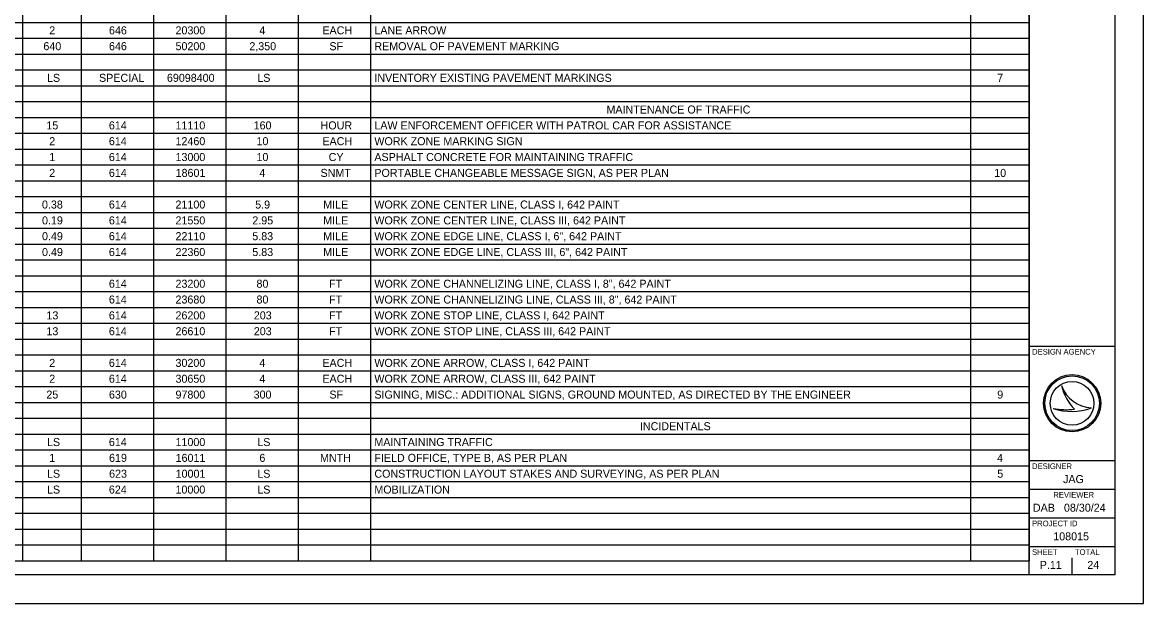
# Model space of a CAD drawing. Extents: x 0 to 34, y 0 to 22.
# Drawn here: x 14.4 to 34, y 0 to 10.16 of the extents above; entities that cross this region are included whole.
import ezdxf

# ---------------------------------------------------------------- set-up
doc = ezdxf.new("R2010")
doc.units = 0
for name, color, linetype in [('Default', 7, 'Continuous'), ('SH_Border', 7, 'Continuous'), ('SH_Cut_Line', 7, 'Continuous'), ('SH_Data', 7, 'Continuous')]:
    doc.layers.add(name, color=color, linetype=linetype)

msp = doc.modelspace()

# ---------------------------------------------------------------- linework, layer by layer
at = {"layer": 'Default'}
for p, q in [((14.396, 10.432), (14.396, 10.155)), ((15.424, 10.432), (15.424, 10.155)), ((16.689, 10.432), (16.689, 10.155)), ((17.954, 10.432), (17.954, 10.155)), ((19.219, 10.432), (19.219, 10.155)), ((20.484, 10.432), (20.484, 10.155)), ((30.972, 10.432), (30.972, 10.155)), ((32, 10.432), (32, 10.155)), ((13.368, 10.155), (14.396, 10.155)), ((14.396, 10.155), (30.972, 10.155)), ((14.396, 10.155), (14.396, 9.878)), ((15.424, 10.155), (15.424, 9.878)), ((16.689, 10.155), (16.689, 9.878)), ((17.954, 10.155), (17.954, 9.878)), ((19.219, 10.155), (19.219, 9.878)), ((20.484, 10.155), (20.484, 9.878)), ((30.972, 10.155), (32, 10.155)), ((30.972, 10.155), (30.972, 9.878)), ((32, 10.155), (32, 9.878)), ((13.368, 9.878), (14.396, 9.878)), ((14.396, 9.878), (30.972, 9.878)), ((14.396, 9.878), (14.396, 9.048)), ((15.424, 9.878), (15.424, 9.048)), ((16.689, 9.878), (16.689, 9.048)), ((17.954, 9.878), (17.954, 9.048)), ((19.219, 9.878), (19.219, 9.048)), ((20.484, 9.878), (20.484, 9.048)), ((30.972, 9.878), (32, 9.878)), ((30.972, 9.878), (30.972, 9.048)), ((32, 9.878), (32, 9.048)), ((13.368, 9.602), (14.396, 9.602)), ((14.396, 9.602), (30.972, 9.602)), ((30.972, 9.602), (32, 9.602)), ((13.368, 9.325), (14.396, 9.325)), ((14.396, 9.325), (30.972, 9.325)), ((30.972, 9.325), (32, 9.325)), ((13.368, 9.048), (14.396, 9.048)), ((14.396, 9.048), (30.972, 9.048)), ((14.396, 9.048), (14.396, 8.495)), ((15.424, 9.048), (15.424, 8.495)), ((16.689, 9.048), (16.689, 8.495)), ((17.954, 9.048), (17.954, 8.495)), ((19.219, 9.048), (19.219, 8.495)), ((20.484, 9.048), (20.484, 8.495)), ((30.972, 9.048), (32, 9.048)), ((30.972, 9.048), (30.972, 8.495)), ((32, 9.048), (32, 8.495)), ((13.368, 8.772), (14.396, 8.772)), ((14.396, 8.772), (30.972, 8.772)), ((30.972, 8.772), (32, 8.772)), ((13.368, 8.495), (14.396, 8.495)), ((14.396, 8.495), (30.972, 8.495)), ((14.396, 8.495), (14.396, 7.665)), ((15.424, 8.495), (15.424, 7.665)), ((16.689, 8.495), (16.689, 7.665)), ((17.954, 8.495), (17.954, 7.665)), ((19.219, 8.495), (19.219, 7.665)), ((20.484, 8.495), (20.484, 7.665)), ((30.972, 8.495), (32, 8.495)), ((30.972, 8.495), (30.972, 7.665)), ((32, 8.495), (32, 7.665)), ((13.368, 8.218), (14.396, 8.218)), ((14.396, 8.218), (30.972, 8.218)), ((30.972, 8.218), (32, 8.218)), ((13.368, 7.941), (14.396, 7.941)), ((14.396, 7.941), (30.972, 7.941)), ((30.972, 7.941), (32, 7.941)), ((13.368, 7.665), (14.396, 7.665)), ((14.396, 7.665), (30.972, 7.665)), ((14.396, 7.665), (14.396, 7.111)), ((15.424, 7.665), (15.424, 7.111)), ((16.689, 7.665), (16.689, 7.111)), ((17.954, 7.665), (17.954, 7.111)), ((19.219, 7.665), (19.219, 7.111)), ((20.484, 7.665), (20.484, 7.111)), ((30.972, 7.665), (32, 7.665)), ((30.972, 7.665), (30.972, 7.111)), ((32, 7.665), (32, 7.111)), ((13.368, 7.388), (14.396, 7.388)), ((14.396, 7.388), (30.972, 7.388)), ((30.972, 7.388), (32, 7.388)), ((13.368, 7.111), (14.396, 7.111)), ((14.396, 7.111), (30.972, 7.111)), ((14.396, 7.111), (14.396, 6.281)), ((15.424, 7.111), (15.424, 6.281)), ((16.689, 7.111), (16.689, 6.281)), ((17.954, 7.111), (17.954, 6.281)), ((19.219, 7.111), (19.219, 6.281)), ((20.484, 7.111), (20.484, 6.281)), ((30.972, 7.111), (32, 7.111)), ((30.972, 7.111), (30.972, 6.281)), ((32, 7.111), (32, 6.281)), ((13.368, 6.835), (14.396, 6.835)), ((14.396, 6.835), (30.972, 6.835)), ((30.972, 6.835), (32, 6.835)), ((13.368, 6.558), (14.396, 6.558)), ((14.396, 6.558), (30.972, 6.558)), ((30.972, 6.558), (32, 6.558)), ((13.368, 6.281), (14.396, 6.281)), ((14.396, 6.281), (30.972, 6.281)), ((14.396, 6.281), (14.396, 5.174)), ((15.424, 6.281), (15.424, 5.174)), ((16.689, 6.281), (16.689, 5.174)), ((17.954, 6.281), (17.954, 5.174)), ((19.219, 6.281), (19.219, 5.174)), ((20.484, 6.281), (20.484, 5.174)), ((30.972, 6.281), (32, 6.281)), ((30.972, 6.281), (30.972, 5.174)), ((32, 6.281), (32, 5.174)), ((13.368, 6.004), (14.396, 6.004)), ((14.396, 6.004), (30.972, 6.004)), ((30.972, 6.004), (32, 6.004)), ((13.368, 5.728), (14.396, 5.728)), ((14.396, 5.728), (30.972, 5.728)), ((30.972, 5.728), (32, 5.728)), ((13.368, 5.451), (14.396, 5.451)), ((14.396, 5.451), (30.972, 5.451)), ((30.972, 5.451), (32, 5.451)), ((13.368, 5.174), (14.396, 5.174)), ((14.396, 5.174), (30.972, 5.174)), ((14.396, 5.174), (14.396, 4.898)), ((15.424, 5.174), (15.424, 4.898)), ((16.689, 5.174), (16.689, 4.898)), ((17.954, 5.174), (17.954, 4.898)), ((19.219, 5.174), (19.219, 4.898)), ((20.484, 5.174), (20.484, 4.898)), ((30.972, 5.174), (32, 5.174)), ((30.972, 5.174), (30.972, 4.898)), ((32, 5.174), (32, 4.898)), ((13.368, 4.898), (14.396, 4.898)), ((14.396, 4.898), (30.972, 4.898)), ((14.396, 4.898), (14.396, 3.791)), ((15.424, 4.898), (15.424, 3.791)), ((16.689, 4.898), (16.689, 3.791)), ((17.954, 4.898), (17.954, 3.791)), ((19.219, 4.898), (19.219, 3.791)), ((20.484, 4.898), (20.484, 3.791)), ((30.972, 4.898), (32, 4.898)), ((30.972, 4.898), (30.972, 3.791)), ((32, 4.898), (32, 3.791)), ((13.368, 4.621), (14.396, 4.621)), ((14.396, 4.621), (30.972, 4.621)), ((30.972, 4.621), (32, 4.621)), ((13.368, 4.344), (14.396, 4.344)), ((14.396, 4.344), (30.972, 4.344)), ((30.972, 4.344), (32, 4.344)), ((13.368, 4.068), (14.396, 4.068)), ((14.396, 4.068), (30.972, 4.068)), ((30.972, 4.068), (32, 4.068)), ((13.368, 3.791), (14.396, 3.791)), ((14.396, 3.791), (30.972, 3.791)), ((14.396, 3.791), (14.396, 3.514)), ((15.424, 3.791), (15.424, 3.514)), ((16.689, 3.791), (16.689, 3.514)), ((17.954, 3.791), (17.954, 3.514)), ((19.219, 3.791), (19.219, 3.514)), ((20.484, 3.791), (20.484, 3.514)), ((30.972, 3.791), (32, 3.791)), ((30.972, 3.791), (30.972, 3.514)), ((32, 3.791), (32, 3.514)), ((13.368, 3.514), (14.396, 3.514)), ((14.396, 3.514), (30.972, 3.514)), ((14.396, 3.514), (14.396, 2.407)), ((15.424, 3.514), (15.424, 2.407)), ((16.689, 3.514), (16.689, 2.407)), ((17.954, 3.514), (17.954, 2.407)), ((19.219, 3.514), (19.219, 2.407)), ((20.484, 3.514), (20.484, 2.407)), ((30.972, 3.514), (32, 3.514)), ((30.972, 3.514), (30.972, 2.407)), ((32, 3.514), (32, 2.407)), ((13.368, 3.237), (14.396, 3.237)), ((14.396, 3.237), (30.972, 3.237)), ((30.972, 3.237), (32, 3.237)), ((13.368, 2.961), (14.396, 2.961)), ((14.396, 2.961), (30.972, 2.961)), ((30.972, 2.961), (32, 2.961)), ((13.368, 2.684), (14.396, 2.684)), ((14.396, 2.684), (30.972, 2.684)), ((30.972, 2.684), (32, 2.684)), ((13.368, 2.407), (14.396, 2.407)), ((14.396, 2.407), (30.972, 2.407)), ((14.396, 2.407), (14.396, 2.131)), ((15.424, 2.407), (15.424, 2.131)), ((16.689, 2.407), (16.689, 2.131)), ((17.954, 2.407), (17.954, 2.131)), ((19.219, 2.407), (19.219, 2.131)), ((20.484, 2.407), (20.484, 2.131)), ((30.972, 2.407), (32, 2.407)), ((30.972, 2.407), (30.972, 2.131)), ((32, 2.407), (32, 2.131)), ((13.368, 2.131), (14.396, 2.131)), ((14.396, 2.131), (30.972, 2.131)), ((14.396, 2.131), (14.396, 1.024)), ((15.424, 2.131), (15.424, 1.024)), ((16.689, 2.131), (16.689, 1.024)), ((17.954, 2.131), (17.954, 1.024)), ((19.219, 2.131), (19.219, 1.024)), ((20.484, 2.131), (20.484, 1.024)), ((30.972, 2.131), (32, 2.131)), ((30.972, 2.131), (30.972, 1.024)), ((32, 2.131), (32, 1.024)), ((13.368, 1.854), (14.396, 1.854)), ((14.396, 1.854), (30.972, 1.854)), ((30.972, 1.854), (32, 1.854)), ((13.368, 1.577), (14.396, 1.577)), ((14.396, 1.577), (30.972, 1.577)), ((30.972, 1.577), (32, 1.577)), ((13.368, 1.3), (14.396, 1.3)), ((14.396, 1.3), (30.972, 1.3)), ((30.972, 1.3), (32, 1.3)), ((13.368, 1.024), (14.396, 1.024)), ((14.396, 1.024), (30.972, 1.024)), ((14.396, 1.024), (14.396, 0.747)), ((15.424, 1.024), (15.424, 0.747)), ((16.689, 1.024), (16.689, 0.747)), ((17.954, 1.024), (17.954, 0.747)), ((19.219, 1.024), (19.219, 0.747)), ((20.484, 1.024), (20.484, 0.747)), ((30.972, 1.024), (32, 1.024)), ((30.972, 1.024), (30.972, 0.747)), ((32, 1.024), (32, 0.747)), ((13.368, 0.747), (14.396, 0.747)), ((14.396, 0.747), (30.972, 0.747)), ((30.972, 0.747), (32, 0.747))]:
    msp.add_line(p, q, dxfattribs=at)
at = {"layer": 'SH_Border'}
for p, q in [((32, 0.5), (32, 21.5)), ((32, 4.5), (33.5, 4.5)), ((32, 2.5), (33.5, 2.5)), ((32, 2), (33.5, 2)), ((32, 1.5), (33.5, 1.5)), ((32, 1), (33.5, 1))]:
    msp.add_line(p, q, dxfattribs=at)
msp.add_lwpolyline([(1.5, 21.5), (33.5, 21.5), (33.5, 0.5), (1.5, 0.5)], close=True, dxfattribs=at)
at = {"layer": 'SH_Cut_Line'}
msp.add_lwpolyline([(0, 0), (34, 0), (34, 22), (0, 22)], close=True, dxfattribs=at)
at = {"layer": 'SH_Data'}
for p, q in [((32.567, 3.81), (32.567, 3.81)), ((32.417, 3.41), (32.417, 3.41)), ((32.75, 3.5), (32.75, 3.5)), ((33.087, 3.419), (33.087, 3.419)), ((32.75, 0.5), (32.75, 0.8)), ((32.375, 0.675), (32.375, 0.675))]:
    msp.add_line(p, q, dxfattribs=at)
for radius in [0.5, 0.477, 0.477, 0.382]:
    msp.add_circle((32.75, 3.5), radius, dxfattribs=at)
for centre, radius, start, end in [((33.116, 3.998), 0.58, 198.9257, 198.9319), ((33.347, 3.97), 0.796, 191.6379, 191.6421), ((33.116, 3.998), 0.58, 198.9319, 267.1657), ((33.347, 3.97), 0.796, 191.6421, 226.0947), ((32.739, 4.37), 1.013, 251.4576, 290.0832), ((32.648, 4.654), 1.266, 259.4964, 259.4995), ((32.739, 4.37), 1.013, 251.4527, 251.4576), ((32.648, 4.654), 1.266, 259.4995, 276.6672)]:
    msp.add_arc(centre, radius, start, end, dxfattribs=at)

# ---------------------------------------------------------------- texts
at = {"layer": 'Default'}
for s, p in [('2', (14.865, 9.947)), ('646', (15.91, 9.947)), ('20300', (17.073, 9.947)), ('4', (18.539, 9.947)), ('EACH', (19.641, 9.947)), ('LANE ARROW', (20.55, 9.947)), ('640', (14.763, 9.67)), ('646', (15.91, 9.67)), ('50200', (17.073, 9.67)), ('2,350', (18.364, 9.67)), ('SF', (19.764, 9.67)), ('REMOVAL OF PAVEMENT MARKING', (20.55, 9.67)), ('LS', (14.826, 9.117)), ('SPECIAL', (15.736, 9.117)), ('69098400', (16.923, 9.117)), ('LS', (18.503, 9.117)), ('INVENTORY EXISTING PAVEMENT MARKINGS', (20.55, 9.117)), ('7', (31.44, 9.117)), ('MAINTENANCE OF TRAFFIC', (24.609, 8.563)), ('15', (14.815, 8.286)), ('614', (15.908, 8.286)), ('11110', (17.073, 8.286)), ('160', (18.439, 8.286)), ('HOUR', (19.61, 8.286)), ('LAW ENFORCEMENT OFFICER WITH PATROL CAR FOR ASSISTANCE', (20.55, 8.286)), ('2', (14.865, 8.01)), ('614', (15.908, 8.01)), ('12460', (17.073, 8.01)), ('10', (18.489, 8.01)), ('EACH', (19.641, 8.01)), ('WORK ZONE MARKING SIGN', (20.55, 8.01)), ('1', (14.865, 7.733)), ('614', (15.908, 7.733)), ('13000', (17.073, 7.733)), ('10', (18.489, 7.733)), ('CY', (19.751, 7.733)), ('ASPHALT CONCRETE FOR MAINTAINING TRAFFIC', (20.55, 7.733)), ('2', (14.865, 7.456)), ('614', (15.908, 7.456)), ('18601', (17.075, 7.456)), ('4', (18.539, 7.456)), ('SNMT', (19.609, 7.456)), ('PORTABLE CHANGEABLE MESSAGE SIGN, AS PER PLAN', (20.55, 7.456)), ('10', (31.389, 7.456)), ('0.38', (14.738, 6.903)), ('614', (15.908, 6.903)), ('21100', (17.073, 6.903)), ('5.9', (18.466, 6.903)), ('MILE', (19.656, 6.903)), ('WORK ZONE CENTER LINE, CLASS I, 642 PAINT', (20.55, 6.903)), ('0.19', (14.739, 6.626)), ('614', (15.908, 6.626)), ('21550', (17.073, 6.626)), ('2.95', (18.416, 6.626)), ('MILE', (19.656, 6.626)), ('WORK ZONE CENTER LINE, CLASS III, 642 PAINT', (20.55, 6.626)), ('0.49', (14.739, 6.35)), ('614', (15.908, 6.35)), ('22110', (17.073, 6.35)), ('5.83', (18.416, 6.35)), ('MILE', (19.656, 6.35)), ('WORK ZONE EDGE LINE, CLASS I, 6", 642 PAINT', (20.55, 6.35)), ('0.49', (14.739, 6.073)), ('614', (15.908, 6.073)), ('22360', (17.073, 6.073)), ('5.83', (18.416, 6.073)), ('MILE', (19.656, 6.073)), ('WORK ZONE EDGE LINE, CLASS III, 6", 642 PAINT', (20.55, 6.073)), ('614', (15.908, 5.519)), ('23200', (17.073, 5.519)), ('80', (18.489, 5.519)), ('FT', (19.758, 5.519)), ('WORK ZONE CHANNELIZING LINE, CLASS I, 8", 642 PAINT', (20.55, 5.519)), ('614', (15.908, 5.243)), ('23680', (17.073, 5.243)), ('80', (18.489, 5.243)), ('FT', (19.758, 5.243)), ('WORK ZONE CHANNELIZING LINE, CLASS III, 8", 642 PAINT', (20.55, 5.243)), ('13', (14.816, 4.966)), ('614', (15.908, 4.966)), ('26200', (17.073, 4.966)), ('203', (18.442, 4.966)), ('FT', (19.758, 4.966)), ('WORK ZONE STOP LINE, CLASS I, 642 PAINT', (20.55, 4.966)), ('13', (14.816, 4.689)), ('614', (15.908, 4.689)), ('26610', (17.073, 4.689)), ('203', (18.442, 4.689)), ('FT', (19.758, 4.689)), ('WORK ZONE STOP LINE, CLASS III, 642 PAINT', (20.55, 4.689)), ('2', (14.865, 4.136)), ('614', (15.908, 4.136)), ('30200', (17.073, 4.136)), ('4', (18.539, 4.136)), ('EACH', (19.641, 4.136)), ('WORK ZONE ARROW, CLASS I, 642 PAINT', (20.55, 4.136)), ('2', (14.865, 3.859)), ('614', (15.908, 3.859)), ('30650', (17.073, 3.859)), ('4', (18.539, 3.859)), ('EACH', (19.641, 3.859)), ('WORK ZONE ARROW, CLASS III, 642 PAINT', (20.55, 3.859)), ('25', (14.815, 3.582)), ('630', (15.909, 3.582)), ('97800', (17.073, 3.582)), ('300', (18.439, 3.582)), ('SF', (19.764, 3.582)), ('SIGNING, MISC.: ADDITIONAL SIGNS, GROUND MOUNTED, AS DIRECTED BY THE ENGINEER', (20.55, 3.582)), ('9', (31.441, 3.582)), ('INCIDENTALS', (25.193, 3.029)), ('LS', (14.826, 2.752)), ('614', (15.908, 2.752)), ('11000', (17.073, 2.752)), ('LS', (18.503, 2.752)), ('MAINTAINING TRAFFIC', (20.55, 2.752)), ('1', (14.865, 2.476)), ('619', (15.911, 2.476)), ('16011', (17.075, 2.476)), ('6', (18.54, 2.476)), ('MNTH', (19.6, 2.476)), ('FIELD OFFICE, TYPE B, AS PER PLAN', (20.55, 2.476)), ('4', (31.439, 2.476)), ('LS', (14.826, 2.199)), ('623', (15.912, 2.199)), ('10001', (17.075, 2.199)), ('LS', (18.503, 2.199)), ('CONSTRUCTION LAYOUT STAKES AND SURVEYING, AS PER PLAN', (20.55, 2.199)), ('5', (31.442, 2.199)), ('LS', (14.826, 1.922)), ('624', (15.908, 1.922)), ('10000', (17.073, 1.922)), ('LS', (18.503, 1.922)), ('MOBILIZATION', (20.55, 1.922))]:
    msp.add_text(s, height=0.14, dxfattribs=at).set_placement(p)
at = {"layer": 'SH_Data'}
for s, height, p in [('DESIGN AGENCY', 0.1, (32.05, 4.35)), ('DESIGNER', 0.1, (32.05, 2.35)), ('JAG', 0.14, (32.592, 2.105)), ('REVIEWER', 0.1, (32.422, 1.85)), ('DAB', 0.14, (32.065, 1.605)), ('08/30/24', 0.14, (32.608, 1.605)), ('PROJECT ID', 0.1, (32.05, 1.35)), ('108015', 0.14, (32.421, 1.105)), ('SHEET', 0.1, (32.05, 0.85)), ('TOTAL', 0.1, (32.8, 0.85)), ('P.11', 0.14, (32.184, 0.605)), ('24', 0.14, (33.016, 0.605))]:
    msp.add_text(s, height=height, dxfattribs=at).set_placement(p)

doc.saveas('drawing.dxf')
